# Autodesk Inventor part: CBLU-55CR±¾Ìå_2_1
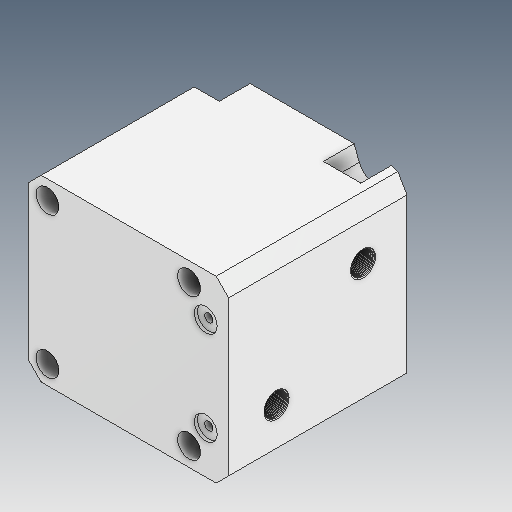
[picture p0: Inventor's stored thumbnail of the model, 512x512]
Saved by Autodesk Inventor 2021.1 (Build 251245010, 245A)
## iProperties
Created: 2021-05
Part Number: CBLU-55CR±¾Ìå_2_1
Material: Ogólny
Document SubType Name: Modeling
Designer: user
Density: 1 g/cm^3
Appearance: Domyślna
Author: user
Revision Number: ÈÎºÎ
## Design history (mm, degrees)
feature "ÊäÈë1"
feature "ÊäÈë3"
feature "ÇÐ³ý-À­Éì1" [ÊäÈë]
node "Bryła1"
node "Bryła2"
node "Bryła3"
